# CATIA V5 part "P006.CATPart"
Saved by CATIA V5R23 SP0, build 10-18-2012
Part number: P006
Definition: Rondelle
Bounding box of the stored display mesh (mm): x -2.5 to 2.5, y -14 to 14, z -13.952 to 13.952
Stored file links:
  C:\wamp\www\COURS\CONCEPTION GMP1\TITRE 02-SEMESTRE 2\03-TP7-PRESSE MECANIQUE\eleve\P006.CATPart
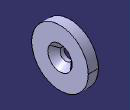
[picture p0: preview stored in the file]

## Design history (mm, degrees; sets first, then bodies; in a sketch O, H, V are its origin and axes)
Body1 (main body)
  Sketch1 on yz-plane, origin (0, 0, 0), H (0, 1, 0), V (0, 0, 1)
    circle A1 centre (0, 0) radius 14
    radius A1 = 14
  Pad1: profile Sketch1, direction (1, 0, 0), length 2.5, mirrored extent
  Sketch2 on face of Pad1, origin (2.5, 0, 0), H (0, 1, 0), V (0, 0, 1)
    point P1 (0, 0)
  Hole1: placed by Sketch2, at (2.5, 0, 0) direction (-1, 0, 0), diameter 6, through (limit type 3), countersink depth 3, countersink angle 90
